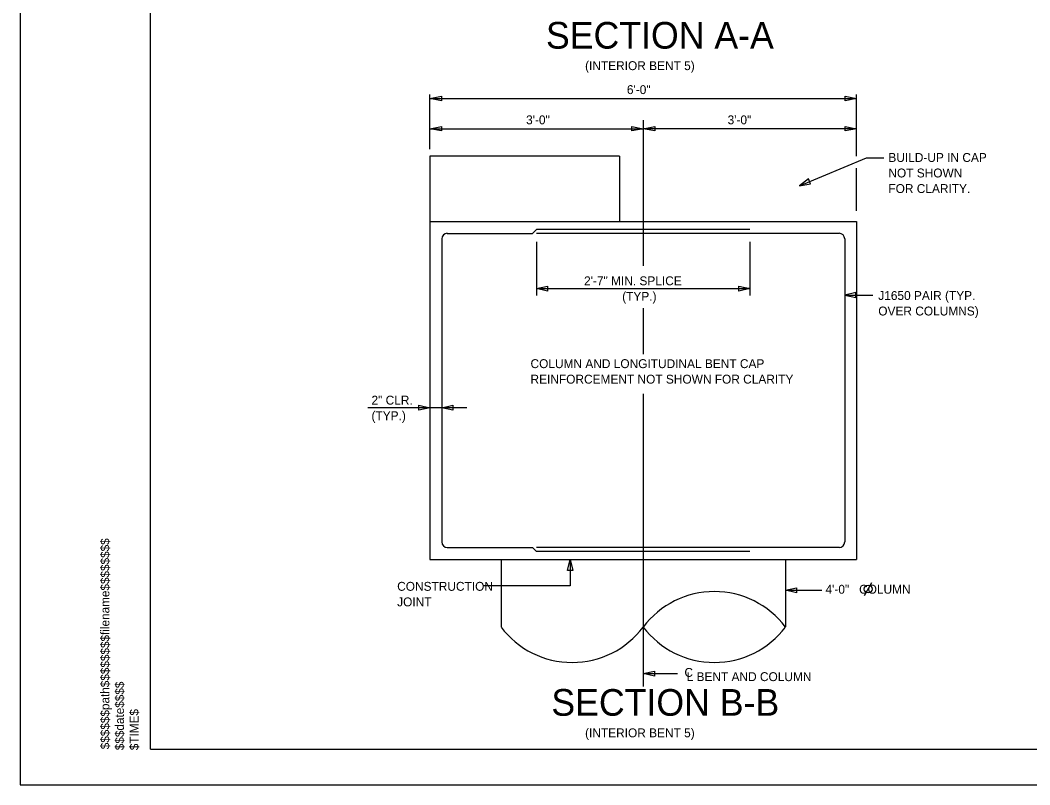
# Model space of a CAD drawing. Extents: x -133.1 to -97, y -1.7 to 20.3.
# Drawn here: x -133.14 to -118.94, y -1.69 to 9.06 of the extents above; entities that cross this region are included whole.
import ezdxf

# ---------------------------------------------------------------- set-up
doc = ezdxf.new("R2010")
doc.units = 0
for name, color, linetype in [('BR_AUTO DIMENSION', 7, 'Continuous'), ('BR_BORDER LINES', 7, 'Continuous'), ('BR_CENTER LINES', 7, 'Continuous'), ('BR_CONCRETE', 7, 'Continuous'), ('BR_REBAR', 7, 'Continuous'), ('BR_TEXT', 7, 'Continuous'), ('Level 31', 7, 'Continuous'), ('RD_SHT_ID', 7, 'Continuous')]:
    doc.layers.add(name, color=color, linetype=linetype)

msp = doc.modelspace()

# ---------------------------------------------------------------- linework, layer by layer
at = {"layer": 'BR_AUTO DIMENSION'}
for p, q in [((-127.38, 7.245), (-127.38, 8.016)), ((-127.38, 7.959), (-121.38, 7.959)), ((-121.38, 7.146), (-121.38, 8.016)), ((-127.38, 7.534), (-124.38, 7.534)), ((-121.38, 7.534), (-124.38, 7.534)), ((-122.185, 6.729), (-121.239, 7.126)), ((-121.239, 7.126), (-120.995, 7.126)), ((-121.38, 6.378), (-121.38, 6.978)), ((-125.88, 5.942), (-125.88, 5.189)), ((-122.88, 5.942), (-122.88, 5.189)), ((-125.88, 5.286), (-122.88, 5.286)), ((-121.546, 5.195), (-121.151, 5.195)), ((-126.862, 3.611), (-128.254, 3.611)), ((-125.407, 1.479), (-125.407, 1.106)), ((-125.407, 1.106), (-126.63, 1.106)), ((-122.38, 1.044), (-121.868, 1.044)), ((-124.38, -0.128), (-123.897, -0.128))]:
    msp.add_line(p, q, dxfattribs=at)
for points in [[(-127.217, 7.927), (-127.38, 7.959), (-127.217, 7.99)], [(-121.542, 7.99), (-121.38, 7.959), (-121.542, 7.927)], [(-127.217, 7.502), (-127.38, 7.534), (-127.217, 7.565)], [(-124.542, 7.565), (-124.38, 7.534), (-124.542, 7.502)], [(-124.217, 7.502), (-124.38, 7.534), (-124.217, 7.565)], [(-121.542, 7.565), (-121.38, 7.534), (-121.542, 7.502)], [(-122.058, 6.827), (-122.185, 6.729), (-122.028, 6.761)], [(-125.724, 5.25), (-125.88, 5.286), (-125.724, 5.322)], [(-123.036, 5.322), (-122.88, 5.286), (-123.036, 5.25)], [(-121.39, 5.231), (-121.546, 5.195), (-121.39, 5.159)], [(-127.536, 3.647), (-127.38, 3.611), (-127.536, 3.575)], [(-127.057, 3.575), (-127.213, 3.611), (-127.057, 3.647)], [(-125.443, 1.323), (-125.407, 1.479), (-125.371, 1.323)], [(-122.224, 1.008), (-122.38, 1.044), (-122.224, 1.08)], [(-124.224, -0.164), (-124.38, -0.128), (-124.224, -0.092)]]:
    msp.add_lwpolyline(points, close=True, dxfattribs=at)
at = {"layer": 'BR_BORDER LINES'}
for q in [(-131.308, 19.809), (-97.642, -1.191)]:
    msp.add_line((-131.308, -1.191), q, dxfattribs=at)
at = {"layer": 'BR_CENTER LINES'}
for p, q in [((-124.38, 7.655), (-124.38, 5.605)), ((-124.38, 5.011), (-124.38, 4.363)), ((-124.38, 3.808), (-124.38, -0.307))]:
    msp.add_line(p, q, dxfattribs=at)
at = {"layer": 'BR_CONCRETE'}
for p, q in [((-127.38, 7.146), (-127.38, 1.479)), ((-124.713, 7.146), (-127.38, 7.146)), ((-124.713, 7.146), (-124.713, 6.229)), ((-127.38, 6.229), (-121.38, 6.229)), ((-121.38, 6.229), (-121.38, 1.479)), ((-127.38, 1.479), (-126.38, 1.479)), ((-126.38, 1.479), (-126.38, 0.528)), ((-126.38, 1.479), (-122.38, 1.479)), ((-122.38, 1.479), (-121.38, 1.479)), ((-122.38, 1.479), (-122.38, 0.528))]:
    msp.add_line(p, q, dxfattribs=at)
for centre, start, end in [((-123.38, -0.226), 37.0023, 142.9977), ((-125.38, 1.281), 217.0023, 322.9977), ((-123.38, 1.281), 217.0023, 322.9977)]:
    msp.add_arc(centre, 1.252, start, end, dxfattribs=at)
at = {"layer": 'BR_REBAR'}
for p, q in [((-125.935, 6.063), (-125.88, 6.118)), ((-122.88, 6.118), (-125.88, 6.118)), ((-127.213, 5.985), (-127.213, 1.724)), ((-127.135, 6.063), (-125.935, 6.063)), ((-121.624, 6.063), (-125.88, 6.063)), ((-121.546, 5.985), (-121.546, 1.724)), ((-127.135, 1.646), (-125.935, 1.646)), ((-125.935, 1.646), (-125.88, 1.591)), ((-121.622, 1.646), (-125.88, 1.646)), ((-122.88, 1.591), (-125.88, 1.591))]:
    msp.add_line(p, q, dxfattribs=at)
for centre, start, end in [((-127.135, 5.985), 90, 180), ((-121.625, 5.985), 360, 90), ((-127.135, 1.724), 180, 270), ((-121.625, 1.724), 270, 360)]:
    msp.add_arc(centre, 0.0781, start, end, dxfattribs=at)
at = {"layer": 'BR_TEXT'}
for p, q in [((-125.88, 5.286), (-125.802, 5.286)), ((-122.88, 5.286), (-122.977, 5.286)), ((-121.27, 0.971), (-121.165, 1.153))]:
    msp.add_line(p, q, dxfattribs=at)
msp.add_circle((-121.218, 1.062), 0.055, dxfattribs=at)
at = {"layer": 'Level 31'}
msp.add_lwpolyline([(-133.141, -1.691), (-97.141, -1.691), (-97.141, 20.309), (-133.141, 20.309)], close=True, dxfattribs=at)

# ---------------------------------------------------------------- texts
at = {"layer": 'BR_AUTO DIMENSION'}
for s, p in [('6\'-0"', (-124.61, 8.021)), ('3\'-0"', (-126.027, 7.596)), ('3\'-0"', (-123.194, 7.596))]:
    msp.add_text(s, height=0.125, dxfattribs=at).set_placement(p)
at = {"layer": 'BR_TEXT'}
for s, p in [('SECTION A-A', (-125.748, 8.66)), ('SECTION B-B', (-125.672, -0.72))]:
    msp.add_text(s, height=0.375, dxfattribs=at).set_placement(p)
for s, p in [('(INTERIOR BENT 5)', (-125.198, 8.358)), ('BUILD-UP IN CAP', (-120.933, 7.067)), ('NOT SHOWN', (-120.933, 6.849)), ('FOR CLARITY.', (-120.933, 6.63)), ('2\'-7" MIN. SPLICE', (-125.212, 5.333)), ('J1650 PAIR (TYP.', (-121.075, 5.126)), ('(TYP.)', (-124.676, 5.114)), ('OVER COLUMNS)', (-121.075, 4.908)), ('COLUMN AND LONGITUDINAL BENT CAP', (-125.965, 4.168)), ('REINFORCEMENT NOT SHOWN FOR CLARITY', (-125.965, 3.95)), ('2" CLR.', (-128.201, 3.655)), ('(TYP.)', (-128.201, 3.436)), ('CONSTRUCTION', (-127.84, 1.037)), ('4\'-0"   COLUMN', (-121.817, 0.996)), ('JOINT', (-127.84, 0.818)), ('C', (-123.801, -0.173)), ('L BENT AND COLUMN', (-123.77, -0.233)), ('(INTERIOR BENT 5)', (-125.198, -1.023))]:
    msp.add_text(s, height=0.125, rotation=360, dxfattribs=at).set_placement(p)
at = {"layer": 'RD_SHT_ID'}
for s, height, p in [('$$$$$$path$$$$$$$$filename$$$$$$$$', 0.12347, (-131.887, -1.191)), ('$$$date$$$$', 0.12347, (-131.682, -1.204)), ('$TIME$', 0.1235, (-131.477, -1.204))]:
    msp.add_text(s, height=height, rotation=90, dxfattribs=at).set_placement(p)

doc.saveas('drawing.dxf')
